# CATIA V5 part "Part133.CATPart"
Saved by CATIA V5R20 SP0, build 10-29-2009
Part number: FA 084700-2 comprimido
Revision: ANY
Definition: UNKNOWN
Nomenclature: FA 084700-2 comprimido
Source: Unknown
Bounding box of the stored display mesh (mm): x -2.45 to 2.45, y 0 to 4.72, z -2.45 to 2.45
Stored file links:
  C:\Users\Utente\Desktop\IO LAVORO\3D X SITO CF\CUMSA\3D files FA\FA 084712-20\Part133.CATPart

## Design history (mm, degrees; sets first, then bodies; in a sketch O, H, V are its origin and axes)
Body1 "Cortar-Extruir1" (main body)
  Solid1: solid without history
